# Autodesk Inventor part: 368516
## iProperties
Created: 2006-06
Part Number: 368516
Material: FSt
Description: Sicherungsring
Vendor: Autodesk Inc.
Document SubType Name: Modeling
Standard: DIN 471
Designer: I.Baliuc
Standards Organization: DIN
Language: de-DE
Size Designation: 22 x 1.2
Categories: <MemberInstance Version="R10.0.0"><Categories><Category DisplayName="Wellenteile" InternalName="7f7aeb1f-a693-4053-b835-cee3144e0d98" Mnemonic="SHFT"><Category
Density: 7.85 g/cm^3
Mass: 2.24238 g
Surface Area: 6.83159 cm^2
Volume: 0.285653 cm^3
Abmessung: 22 x 1.2
Author: T.Messerschmitt
Comments: DIN 471 - 22 x 1.2
Revision Number: 368516
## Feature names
1. Körper [Extrusion]
